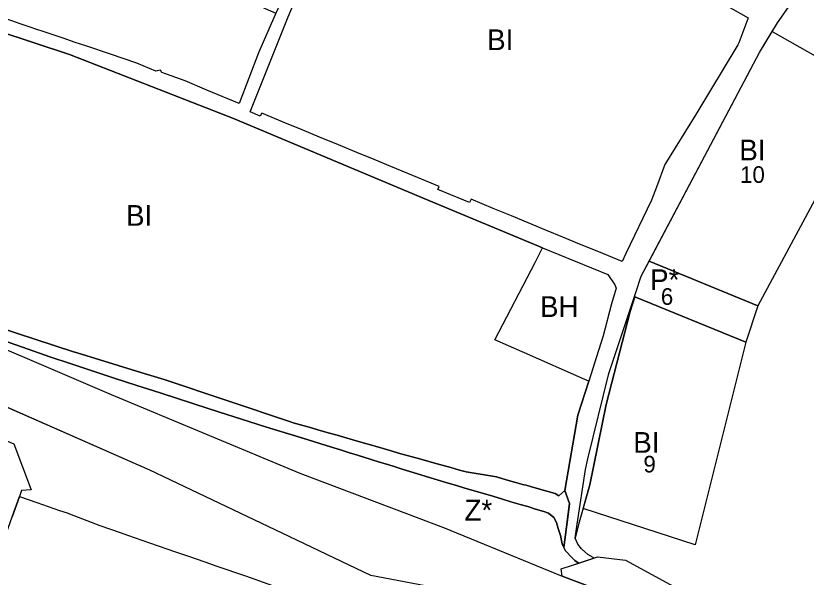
# Model space of a CAD drawing. Extents: x -521621 to -516769, y -1190068 to -1185078.
# Drawn here: x -518605.8 to -518225.8, y -1187311.1 to -1187040.9 of the extents above; entities that cross this region are included whole.
import ezdxf

# ---------------------------------------------------------------- set-up
doc = ezdxf.new("R2010")
doc.units = 0
for name, color, linetype in [('bydleni_n', 7, 'Continuous'), ('bydleni_s', 7, 'Continuous'), ('fpl_id', 7, 'Continuous'), ('s_zelen_s', 7, 'Continuous'), ('v_infrastr_n', 7, 'Continuous'), ('v_infrastr_s', 7, 'Continuous')]:
    doc.layers.add(name, color=color, linetype=linetype)

msp = doc.modelspace()

# ---------------------------------------------------------------- linework, layer by layer
at = {"layer": 'bydleni_n'}
for points in [[(-518301.26, -1187159.09), (-518248.17, -1187058.62), (-518242.06, -1187048.54), (-518220.38, -1187060.82), (-518193.01, -1187076.32), (-518248.95, -1187180.44)], [(-518248.95, -1187180.44), (-518301.26, -1187159.09)], [(-518254.78, -1187197.93), (-518279.15, -1187295.59), (-518332.99, -1187278.06), (-518329.79, -1187266.69), (-518321.96, -1187227.97), (-518310.32, -1187183.32), (-518308.17, -1187176.14)], [(-518308.17, -1187176.14), (-518254.78, -1187197.93)]]:
    msp.add_lwpolyline(points, dxfattribs=at)
at = {"layer": 'bydleni_s'}
for p, q in [((-518414.55, -1187117.99), (-518425.55, -1187113.44)), ((-518402.17, -1187123.11), (-518414.55, -1187117.99)), ((-518376.24, -1187133.63), (-518386.9, -1187129.24)), ((-518367.43, -1187137.27), (-518376.24, -1187133.63)), ((-518359.52, -1187140.53), (-518367.43, -1187137.27)), ((-518350.66, -1187144.18), (-518359.52, -1187140.53)), ((-518342.78, -1187147.43), (-518350.66, -1187144.18)), ((-518334.7, -1187150.76), (-518342.78, -1187147.43))]:
    msp.add_line(p, q, dxfattribs=at)
for points in [[(-518465.82, -1187019.86), (-518456.99, -1187002.02), (-518440.92, -1186969.52), (-518428.52, -1186944.97), (-518427.64, -1186943.43), (-518253.7, -1187041.94), (-518253.88, -1187042.41), (-518258.22, -1187053.89), (-518258.57, -1187054.82), (-518278.8, -1187088.37), (-518293.65, -1187112.46), (-518297.8, -1187123.36), (-518300.17, -1187129.58), (-518312.46, -1187155.36), (-518314.28, -1187159.18), (-518325.47, -1187154.57)], [(-518433.57, -1187110.12), (-518441.83, -1187106.71), (-518450.69, -1187103.04), (-518459.83, -1187099.26), (-518468.13, -1187095.83), (-518476.44, -1187092.39), (-518487.49, -1187087.82), (-518488.23, -1187089.2), (-518493.04, -1187087.16), (-518474.86, -1187041.46), (-518465.82, -1187019.86)], [(-518491.05, -1187034.9), (-518485.93, -1187037.37), (-518480.71, -1187039.72), (-518489.07, -1187058.7)], [(-518679.09, -1187169.6), (-518578.03, -1187202.6), (-518576.26, -1187203.11), (-518545.72, -1187212.65), (-518534.43, -1187216.02), (-518473.22, -1187236.53), (-518472.37, -1187236.78), (-518470.62, -1187237.28), (-518463.62, -1187239.29), (-518460.05, -1187240.32), (-518454.9, -1187241.8), (-518451.33, -1187242.83), (-518448.05, -1187243.78), (-518443.68, -1187245.04), (-518439.91, -1187246.12), (-518434.18, -1187247.77), (-518433.08, -1187248.09), (-518429.22, -1187249.23), (-518425.36, -1187250.38), (-518421.82, -1187251.42), (-518411.07, -1187254.36), (-518409.46, -1187254.81), (-518403.19, -1187256.57), (-518396.6, -1187258.41), (-518392.5, -1187259.56), (-518389.19, -1187260.49), (-518374.67, -1187262.84), (-518369.95, -1187264.19), (-518365.95, -1187265.34), (-518361.48, -1187266.62), (-518360.48, -1187266.9), (-518358.24, -1187267.54), (-518354.52, -1187268.61), (-518350.46, -1187269.77), (-518346.45, -1187270.92), (-518344.64, -1187271.89), (-518341.86, -1187269.39), (-518335.49, -1187233.19), (-518330.31, -1187216.77), (-518332.18, -1187216.02), (-518361.17, -1187203.14), (-518362.31, -1187202.64), (-518375.39, -1187196.83), (-518356.06, -1187159.68), (-518352.57, -1187152.62), (-518409.17, -1187129.08), (-518501.21, -1187090.33), (-518580.04, -1187059.55), (-518632.58, -1187042.27)], [(-518582.5, -1187051.91), (-518593.56, -1187048.16), (-518594.75, -1187047.76), (-518600.34, -1187045.87), (-518603.73, -1187044.72), (-518607.65, -1187043.39)], [(-518571.72, -1187055.57), (-518577.69, -1187053.54), (-518582.5, -1187051.91)], [(-518560.23, -1187059.46), (-518571.72, -1187055.57)], [(-518489.07, -1187058.7), (-518498.38, -1187083.17), (-518513.93, -1187076.67)], [(-518547.58, -1187063.75), (-518560.23, -1187059.46)], [(-518536.18, -1187067.15), (-518538.44, -1187067.5), (-518547.58, -1187063.75)], [(-518524.42, -1187072.29), (-518535.65, -1187068.28), (-518536.18, -1187067.15)], [(-518513.93, -1187076.67), (-518524.42, -1187072.29)], [(-518425.55, -1187113.44), (-518433.57, -1187110.12)], [(-518390.42, -1187129.58), (-518402.83, -1187124.48), (-518402.17, -1187123.11)], [(-518386.9, -1187129.24), (-518387.64, -1187130.78), (-518390.42, -1187129.58)], [(-518325.47, -1187154.57), (-518334.7, -1187150.76)], [(-518607.2, -1187318.4), (-518619.16, -1187314.3), (-518607.59, -1187282.13), (-518604.06, -1187272.32)], [(-518604.06, -1187272.32), (-518595.77, -1187275.19), (-518584.84, -1187278.96), (-518581.18, -1187280.23), (-518580.01, -1187280.67)], [(-518580.01, -1187280.67), (-518565.37, -1187286.23), (-518555.2, -1187289.76), (-518552.12, -1187290.84)], [(-518552.12, -1187290.84), (-518537.28, -1187296)], [(-518537.28, -1187296), (-518529.01, -1187298.87)], [(-518529.01, -1187298.87), (-518522.71, -1187301.06)], [(-518522.71, -1187301.06), (-518514.92, -1187303.77), (-518509.16, -1187305.77), (-518495.4, -1187310.55), (-518482.42, -1187315.06), (-518469.15, -1187319.68)]]:
    msp.add_lwpolyline(points, dxfattribs=at)
msp.add_lwpolyline([(-518375.39, -1187196.83), (-518356.06, -1187159.68), (-518352.57, -1187152.62), (-518321.13, -1187165.45), (-518317.73, -1187170.38), (-518317.11, -1187171.95), (-518319.43, -1187179.48), (-518323.42, -1187194.94), (-518326.61, -1187205.04), (-518330.31, -1187216.77), (-518332.18, -1187216.02), (-518361.17, -1187203.14), (-518362.31, -1187202.64)], close=True, dxfattribs=at)
at = {"layer": 's_zelen_s'}
for points in [[(-518647.32, -1187185.84), (-518559.98, -1187223.23), (-518469.29, -1187261.05), (-518400.17, -1187287.24), (-518380.6, -1187295.26), (-518343.07, -1187310.63), (-518343.61, -1187307.03)], [(-518342.31, -1187296.86), (-518343.16, -1187295.06), (-518343.89, -1187291.11), (-518344.94, -1187287.72), (-518345.82, -1187284.86), (-518347.12, -1187282.36), (-518349.72, -1187280.38), (-518351.94, -1187279.5), (-518355.87, -1187278.32), (-518359.64, -1187277.18), (-518363.24, -1187276.12), (-518367.72, -1187274.79), (-518371.76, -1187273.59), (-518376.41, -1187272.21), (-518390.44, -1187268.05), (-518393.93, -1187267.02), (-518397.95, -1187265.81), (-518404.73, -1187263.76), (-518412.62, -1187261.38), (-518416.39, -1187260.24), (-518420.1, -1187259.09), (-518423.41, -1187258.06), (-518426.98, -1187256.95), (-518430.89, -1187255.74), (-518434.88, -1187254.5), (-518441.58, -1187252.4), (-518445.31, -1187251.23), (-518449.7, -1187249.86), (-518452.95, -1187248.84), (-518456.53, -1187247.72), (-518465.16, -1187245.01), (-518472.02, -1187242.89), (-518474.73, -1187242.06), (-518485.67, -1187238.69), (-518497.26, -1187235.12), (-518507.84, -1187231.68), (-518520.13, -1187227.68), (-518536.36, -1187222.46), (-518547.62, -1187218.83), (-518558.55, -1187215.31), (-518563.36, -1187213.71), (-518579.72, -1187208.26), (-518589.47, -1187205.01), (-518605.3, -1187199.52), (-518609.99, -1187197.89)], [(-518338.32, -1187301.75), (-518341.55, -1187298.45), (-518342.31, -1187296.86)], [(-518335.37, -1187304.2), (-518336.97, -1187303.13), (-518338.32, -1187301.75)], [(-518343.61, -1187307.03), (-518338.64, -1187305.49)], [(-518338.64, -1187305.49), (-518335.15, -1187304.35), (-518335.37, -1187304.2)]]:
    msp.add_lwpolyline(points, dxfattribs=at)
at = {"layer": 'v_infrastr_n'}
msp.add_lwpolyline([(-518301.26, -1187159.09), (-518248.95, -1187180.44), (-518254.78, -1187197.93), (-518308.17, -1187176.14), (-518310.32, -1187183.32), (-518321.96, -1187227.97), (-518329.79, -1187266.69), (-518335.17, -1187285.8), (-518336.91, -1187292.39), (-518335.9, -1187285.67), (-518331.95, -1187259.37), (-518330.73, -1187254.09), (-518320.62, -1187213.04), (-518307.79, -1187174.55), (-518305.03, -1187166.24)], close=True, dxfattribs=at)
msp.add_lwpolyline([(-518606.69, -1187246.95), (-518598.4, -1187269.16), (-518603.01, -1187269.4), (-518604.06, -1187272.32), (-518607.59, -1187282.13)], dxfattribs=at)
at = {"layer": 'v_infrastr_s'}
for p, q in [((-518632.58, -1187042.27), (-518580.04, -1187059.55)), ((-518600.34, -1187045.87), (-518603.73, -1187044.72)), ((-518582.5, -1187051.91), (-518593.56, -1187048.16)), ((-518577.69, -1187053.54), (-518582.5, -1187051.91)), ((-518541.39, -1187259.69), (-518622.62, -1187223.81)), ((-518443.68, -1187245.04), (-518448.05, -1187243.78)), ((-518439.91, -1187246.12), (-518443.68, -1187245.04)), ((-518434.18, -1187247.77), (-518439.91, -1187246.12)), ((-518433.08, -1187248.09), (-518434.18, -1187247.77)), ((-518429.22, -1187249.23), (-518433.08, -1187248.09)), ((-518425.36, -1187250.38), (-518429.22, -1187249.23)), ((-518421.82, -1187251.42), (-518425.36, -1187250.38)), ((-518411.07, -1187254.36), (-518421.82, -1187251.42)), ((-518409.46, -1187254.81), (-518411.07, -1187254.36)), ((-518403.19, -1187256.57), (-518409.46, -1187254.81)), ((-518396.6, -1187258.41), (-518403.19, -1187256.57)), ((-518481.09, -1187288.4), (-518541.39, -1187259.69)), ((-518392.5, -1187259.56), (-518396.6, -1187258.41)), ((-518389.19, -1187260.49), (-518392.5, -1187259.56)), ((-518435.04, -1187310.32), (-518481.09, -1187288.4)), ((-518405.54, -1187315.9), (-518435.04, -1187310.32))]:
    msp.add_line(p, q, dxfattribs=at)
for points in [[(-518433.57, -1186941.43), (-518464.51, -1187005.06), (-518480.71, -1187039.72), (-518489.07, -1187058.7), (-518498.38, -1187083.17)], [(-518493.04, -1187087.16), (-518474.86, -1187041.46), (-518465.82, -1187019.86), (-518456.99, -1187002.02), (-518440.92, -1186969.52), (-518428.52, -1186944.97)], [(-518428.52, -1186944.97), (-518427.64, -1186943.43), (-518253.7, -1187041.94), (-518253.88, -1187042.41), (-518253.88, -1187042.41), (-518258.22, -1187053.89)], [(-518248.17, -1187058.62), (-518239.49, -1187044.29), (-518232, -1187033.55), (-518244.57, -1187026.43), (-518247.09, -1187030.18), (-518390.3, -1186949.06)], [(-518603.73, -1187044.72), (-518607.65, -1187043.39), (-518611.46, -1187042.1)], [(-518593.56, -1187048.16), (-518594.75, -1187047.76), (-518600.34, -1187045.87)], [(-518498.38, -1187083.17), (-518513.93, -1187076.67), (-518524.42, -1187072.29), (-518535.65, -1187068.28), (-518536.18, -1187067.15), (-518538.44, -1187067.5), (-518547.58, -1187063.75), (-518560.23, -1187059.46), (-518571.72, -1187055.57), (-518577.69, -1187053.54)], [(-518258.57, -1187054.82), (-518278.8, -1187088.37), (-518293.65, -1187112.46), (-518297.8, -1187123.36), (-518300.17, -1187129.58)], [(-518258.22, -1187053.89), (-518258.57, -1187054.82)], [(-518305.03, -1187166.24), (-518248.17, -1187058.62)], [(-518580.04, -1187059.55), (-518501.21, -1187090.33), (-518409.17, -1187129.08), (-518352.57, -1187152.62), (-518321.13, -1187165.45), (-518317.73, -1187170.38), (-518317.11, -1187171.95)], [(-518314.28, -1187159.18), (-518325.47, -1187154.57), (-518334.7, -1187150.76), (-518342.78, -1187147.43), (-518350.66, -1187144.18), (-518359.52, -1187140.53), (-518367.43, -1187137.27), (-518376.24, -1187133.63), (-518386.9, -1187129.24), (-518387.64, -1187130.78), (-518390.42, -1187129.58), (-518402.83, -1187124.48), (-518402.17, -1187123.11), (-518414.55, -1187117.99), (-518425.55, -1187113.44), (-518433.57, -1187110.12), (-518441.83, -1187106.71), (-518450.69, -1187103.04), (-518459.83, -1187099.26), (-518468.13, -1187095.83), (-518476.44, -1187092.39), (-518487.49, -1187087.82), (-518488.23, -1187089.2), (-518493.04, -1187087.16)], [(-518300.17, -1187129.58), (-518312.46, -1187155.36)], [(-518312.46, -1187155.36), (-518314.28, -1187159.18)], [(-518331.95, -1187259.37), (-518330.73, -1187254.09), (-518320.62, -1187213.04), (-518307.79, -1187174.55), (-518305.03, -1187166.24)], [(-518448.05, -1187243.78), (-518451.33, -1187242.83), (-518454.9, -1187241.8), (-518460.05, -1187240.32), (-518463.62, -1187239.29), (-518470.62, -1187237.28), (-518472.37, -1187236.78), (-518473.22, -1187236.53), (-518534.43, -1187216.02), (-518545.72, -1187212.65), (-518576.26, -1187203.11), (-518578.03, -1187202.6), (-518679.09, -1187169.6)], [(-518317.11, -1187171.95), (-518319.43, -1187179.48), (-518323.42, -1187194.94), (-518326.61, -1187205.04), (-518330.31, -1187216.77), (-518335.49, -1187233.19), (-518341.86, -1187269.39)], [(-518647.32, -1187185.84), (-518641.27, -1187187.6), (-518633.61, -1187190.05), (-518620.86, -1187194.11), (-518609.99, -1187197.89), (-518605.3, -1187199.52), (-518589.47, -1187205.01), (-518579.72, -1187208.26), (-518563.36, -1187213.71), (-518558.55, -1187215.31), (-518547.62, -1187218.83), (-518536.36, -1187222.46), (-518520.13, -1187227.68), (-518507.84, -1187231.68), (-518497.26, -1187235.12), (-518485.67, -1187238.69), (-518474.73, -1187242.06), (-518465.16, -1187245.01), (-518456.53, -1187247.72)], [(-518647.32, -1187185.84), (-518559.98, -1187223.23)], [(-518706.73, -1187214.89), (-518692.77, -1187220.22), (-518676.25, -1187226.54), (-518677.41, -1187228.78), (-518666.6, -1187231.71), (-518664.87, -1187230.59), (-518632.31, -1187236.3), (-518606.69, -1187246.95), (-518598.4, -1187269.16)], [(-518541.39, -1187259.69), (-518622.62, -1187223.81)], [(-518559.98, -1187223.23), (-518469.29, -1187261.05)], [(-518456.53, -1187247.72), (-518452.95, -1187248.84), (-518449.7, -1187249.86), (-518445.31, -1187251.23)], [(-518445.31, -1187251.23), (-518441.58, -1187252.4), (-518434.88, -1187254.5), (-518430.89, -1187255.74), (-518426.98, -1187256.95), (-518423.41, -1187258.06), (-518420.1, -1187259.09), (-518416.39, -1187260.24), (-518412.62, -1187261.38)], [(-518481.09, -1187288.4), (-518541.39, -1187259.69)], [(-518341.86, -1187269.39), (-518344.64, -1187271.89), (-518346.45, -1187270.92), (-518350.46, -1187269.77), (-518354.52, -1187268.61), (-518358.24, -1187267.54), (-518360.48, -1187266.9), (-518361.48, -1187266.62), (-518365.95, -1187265.34), (-518369.95, -1187264.19), (-518374.67, -1187262.84), (-518389.19, -1187260.49)], [(-518336.91, -1187292.39), (-518335.9, -1187285.67), (-518331.95, -1187259.37)], [(-518469.29, -1187261.05), (-518400.17, -1187287.24)], [(-518412.62, -1187261.38), (-518404.73, -1187263.76), (-518397.95, -1187265.81), (-518393.93, -1187267.02), (-518390.44, -1187268.05), (-518376.41, -1187272.21)], [(-518603.01, -1187269.4), (-518604.06, -1187272.32), (-518595.77, -1187275.19), (-518584.84, -1187278.96), (-518581.18, -1187280.23), (-518580.01, -1187280.67), (-518565.37, -1187286.23), (-518555.2, -1187289.76), (-518552.12, -1187290.84), (-518537.28, -1187296), (-518529.01, -1187298.87), (-518522.71, -1187301.06), (-518514.92, -1187303.77), (-518509.16, -1187305.77), (-518495.4, -1187310.55), (-518482.42, -1187315.06)], [(-518598.4, -1187269.16), (-518603.01, -1187269.4)], [(-518341.86, -1187269.39), (-518339.6, -1187275.71), (-518340.28, -1187281.01), (-518342.31, -1187296.86), (-518341.55, -1187298.45)], [(-518339.6, -1187275.71), (-518341.86, -1187269.39)], [(-518376.41, -1187272.21), (-518371.76, -1187273.59), (-518367.72, -1187274.79), (-518363.24, -1187276.12), (-518359.64, -1187277.18), (-518355.87, -1187278.32), (-518351.94, -1187279.5), (-518349.72, -1187280.38), (-518347.12, -1187282.36)], [(-518347.12, -1187282.36), (-518345.82, -1187284.86), (-518344.94, -1187287.72), (-518343.89, -1187291.11), (-518343.16, -1187295.06), (-518342.31, -1187296.86), (-518339.6, -1187275.71)], [(-518400.17, -1187287.24), (-518380.6, -1187295.26)], [(-518435.04, -1187310.32), (-518481.09, -1187288.4)], [(-518330.67, -1187300.27), (-518333.85, -1187297.41), (-518335.51, -1187295.27), (-518336.91, -1187292.39)], [(-518380.6, -1187295.26), (-518343.07, -1187310.63)], [(-518341.55, -1187298.45), (-518338.32, -1187301.75)], [(-518343.07, -1187310.63), (-518343.61, -1187307.03), (-518338.64, -1187305.49), (-518326.11, -1187301.38), (-518312.56, -1187302.88), (-518287.67, -1187316.52), (-518288.18, -1187320.19)], [(-518338.32, -1187301.75), (-518336.97, -1187303.13), (-518335.37, -1187304.2)], [(-518332.15, -1187303.36), (-518327.83, -1187301.94), (-518328.18, -1187301.73)], [(-518328.18, -1187301.73), (-518330.67, -1187300.27)], [(-518335.37, -1187304.2), (-518335.15, -1187304.35), (-518332.75, -1187303.56), (-518332.15, -1187303.36)], [(-518405.54, -1187315.9), (-518435.04, -1187310.32)], [(-518248.78, -1187337.53), (-518278.17, -1187335.2), (-518343.07, -1187310.63)], [(-518343.07, -1187310.63), (-518278.17, -1187335.2)]]:
    msp.add_lwpolyline(points, dxfattribs=at)

# ---------------------------------------------------------------- texts
at = {"layer": 'bydleni_n'}
for p in [(-518257.92, -1187110.51), (-518308.92, -1187251.26)]:
    msp.add_text('BI', height=10, dxfattribs=at).set_placement(p)
at = {"layer": 'bydleni_s'}
for s, p in [('BI', (-518379.18, -1187057.44)), ('BI', (-518552.81, -1187142)), ('BH', (-518353.76, -1187185.89))]:
    msp.add_text(s, height=10, dxfattribs=at).set_placement(p)
at = {"layer": 'fpl_id'}
for s, p in [('10', (-518257.54, -1187121.35)), ('6', (-518295.64, -1187180.04)), ('9', (-518304.02, -1187260.72))]:
    msp.add_text(s, height=8, dxfattribs=at).set_placement(p)
at = {"layer": 's_zelen_s'}
msp.add_text('Z*', height=10, dxfattribs=at).set_placement((-518390.1, -1187283.89))
at = {"layer": 'v_infrastr_n'}
msp.add_text('P*', height=10, dxfattribs=at).set_placement((-518300.83, -1187172.94))

doc.saveas('drawing.dxf')
